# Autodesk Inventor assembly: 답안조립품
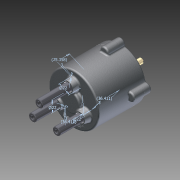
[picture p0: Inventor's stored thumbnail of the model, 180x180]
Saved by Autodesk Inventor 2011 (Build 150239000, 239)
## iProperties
Created: 2015-05
Part Number: 답안조립품
Document SubType Name: Assembly
Designer: Administrator
Author: Administrator
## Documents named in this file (14)
- C:\Documents and Settings\Administrator\바탕 화면\Inventor1급-이근영\답안조립품.iam
- C:\Documents and Settings\Administrator\바탕 화면\Inventor1급-이근영\몸체.ipt
- C:\Documents and Settings\Administrator\바탕 화면\Inventor1급-이근영\커버.ipt
- C:\Documents and Settings\Administrator\바탕 화면\Inventor1급-이근영\오일실.ipt
- C:\Documents and Settings\Administrator\바탕 화면\Inventor1급-이근영\베어링 NA 4900.ipt
- C:\Documents and Settings\Administrator\바탕 화면\Inventor1급-이근영\메인 축.ipt
- C:\Documents and Settings\Administrator\바탕 화면\Inventor1급-이근영\멈춤링 22 x 1.2.ipt
- C:\Documents and Settings\Administrator\바탕 화면\Inventor1급-이근영\판캠.ipt
- C:\Documents and Settings\Administrator\바탕 화면\Inventor1급-이근영\멈춤링 10 x 1.ipt
- C:\Documents and Settings\Administrator\바탕 화면\Inventor1급-이근영\슬라이드 축.ipt
- C:\Documents and Settings\Administrator\바탕 화면\Inventor1급-이근영\가변스프링-11.ipt
- C:\Documents and Settings\Administrator\바탕 화면\Inventor1급-이근영\가변스프링-12.ipt
- C:\Documents and Settings\Administrator\바탕 화면\Inventor1급-이근영\가변스프링-13.ipt
- C:\Documents and Settings\Administrator\바탕 화면\Inventor1급-이근영\M5x0.5x20.ipt
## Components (7 placed, 4 different names)
1. 가변스프링-11:1
2. 가변스프링-12:1
3. 가변스프링-13:1
4. M5x0.5x20:1
5. M5x0.5x20:2
6. M5x0.5x20:3
7. M5x0.5x20:4
